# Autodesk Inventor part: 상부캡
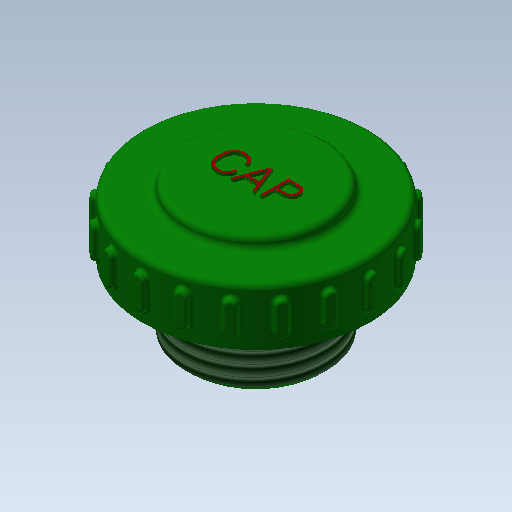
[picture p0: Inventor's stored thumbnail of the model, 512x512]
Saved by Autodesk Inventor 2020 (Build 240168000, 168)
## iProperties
Created: 2015-12
Part Number: 상부캡
Material: PC/ABS 플라스틱
Document SubType Name: Modeling
Designer: mduedu
Density: 7.86 g/cm^3
Appearance: 진녹색
Author: mduedu
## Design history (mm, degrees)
sketch "스케치1"
  geometry: C1 r 12.5 at (0, 0); C2 r 8 at (0, 0); 1 further point
  constraints: 2 centre point, 2 coincident
  dimensions: "d1" = 25 diameter of C1; "d3" = 16 diameter of C2
extrude "돌출1" new body sketch "스케치1" distance "d4" = 12; taper "d6" = 0 deg; dims "d5" = 12, "d7" = 0
sketch "스케치2"
  geometry: C1 r 20 at (0, 0); C2 r 12.5 at (0, 0) reference; 1 further point
  constraints: 1 centre point, 1 coincident
  dimensions: "d8" = 40 diameter of C1
extrude "돌출2" join sketch "스케치2" distance "d10" = 10; taper "d11" = 0 deg
extrude "돌출3" cut sketch "스케치1" extent not by distance; stored distance "d34" = 10; taper "d35" = 0 deg
sketch "스케치5"
  geometry: L1 (-20, 0)-(-20, 10) reference; L2 (-20, 10)-(-12.5, 10) reference; L3 (-12.5, 10)-(-12.5, 12) reference; L4 (-12.5, 12)-(12.5, 12) reference; L5 (12.5, 12)-(12.5, 10) reference; L6 (12.5, 10)-(20, 10) reference; L7 (20, 10)-(20, 0) reference; L8 (20, 0)-(12.5, 0) reference; L9 (12.5, 0)-(12.5, -12) reference; L10 (12.5, -12)-(8, -12) reference; L11 (8, -12)-(8, 0) reference; L12 (8, 0)-(-8, 0) reference; L13 (-8, 0)-(-8, -12) reference; L14 (-8, -12)-(-12.5, -12) reference; L15 (-12.5, -12)-(-12.5, 0) reference; L16 (-12.5, 0)-(-20, 0) reference; L17 (12.5, 0)-(10.5, 0); L18 (10.5, 0)-(10.5, -1); L19 (10.5, -1)-(12.5, -1); L20 (12.5, -1)-(12.5, 0); L21 (0, 0)-(0, 12)
  constraints: 10 end point, 2 parallel, 1 horizontal, 1 midpoint, 1 perpendicular
  dimensions: "d36" = 2 distance of L19.end L18.end; "d37" = 1 distance of L18.end L17.end
revolve "회전1" sketch "스케치5" stored, may be unused: angle "d38" = 90 deg
feature "스레드1" dims "d39" = 10, "d40" = 0
chamfer "모따기3" distance "d41" = 1; stored, may be unused: second distance "d42" = 2, angle "d43" = 45 deg
fillet "모깎기4" dims "d44" = 3
node "작업 평면1"
sketch "스케치7"
  geometry: L1 (1, 0)-(-1, 0); L2 (-1, 0)-(-1, 20.976); L3 (1, 20.976)-(1, 0); C1 r 20 at (0, 0) reference; A1 r 21 centre (0, 0) between (1, 20.976) and (-1, 20.976); 2 further points
  constraints: 6 end point, 2 coincident, 2 point on circle, 1 centre point, 1 horizontal, 1 midpoint, 1 parallel, 1 perpendicular
  dimensions: "d48" = 2 distance of L1.start L1.end; "d49" = 1 radial gap between concentric circles of A1 C1
extrude "돌출4" join sketch "스케치7" distance "d50" = 3; taper "d52" = 0 deg; dims "d51" = 3, "d53" = 0
fillet "모깎기5" dims "d54" = 1
fillet "모깎기6" dims "d55" = 0.5
fillet "모깎기7" dims "d59" = 1
sketch "스케치8"
  geometry: 2 further points
  constraints: 1 coincident, 1 other
feature "엠보싱1" sketch "스케치8" dims "d60" = 0.5, "d61" = 0
node "솔리드1"
pattern_circular "원형 패턴1" dims angle "d57" = 360 deg
node "절단 모서리 투영1"
node "절단 모서리 투영3"
